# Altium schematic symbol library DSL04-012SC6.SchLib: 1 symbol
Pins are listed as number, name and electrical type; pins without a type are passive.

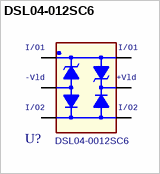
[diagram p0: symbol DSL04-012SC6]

## DSL04-012SC6
designator U?, comment DSL04-0012SC6
footprint ST_SOT23-6L
pins: 1 I/O1, 2 -Vld, 3 I/O2, 4 I/O2b, 5 +Vld, 6 I/O1b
